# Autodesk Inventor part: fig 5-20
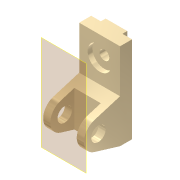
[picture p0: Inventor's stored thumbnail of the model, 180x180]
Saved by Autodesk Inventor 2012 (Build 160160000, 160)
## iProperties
Shininess: 65.0
Angle Display Precision: 2
Document Length Units: 11269
Document Angle Units: 11279
Document Time Units: 11290
Document Mass Units: 11283
Document Length Units Precision: 3
Document Angle Units Precision: 2
Compacted: False
Created: 2001-11
Part Number: fig 5-20
Document SubType Name: Modeling
Designer: Renu Muthoo
Density: 1 g/cm^3
Material: Default
Density: 0.0
Volumn: 0.0
Area: 0.0
PropertySet Name: Model Information
Control State: 0
Master: False
Checked Out: False
Author: Renu Muthoo
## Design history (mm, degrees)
node "Sketch1"
sketch "Sketch2"
  geometry: L1 (33.257, 104.664)-(33.257, -75.336); L2 (33.257, -75.336)-(8.257, -75.336); L3 (8.257, -75.336)-(-45.451, -59.045); L4 (-45.451, -1.628)-(8.257, 14.664); L5 (8.257, 14.664)-(8.257, 104.664); L6 (8.257, 104.664)-(33.257, 104.664); C1 r 15 at (-36.743, -30.336); A1 r 30 centre (-36.743, -30.336) between (-45.451, -1.628) and (-45.451, -59.045)
  constraints: 12 end point, 2 centre point, 2 equal length, 2 parallel, 2 point on circle, 2 tangent, 1 coincident, 1 perpendicular, 1 vertical
  dimensions: "d0" = 180 distance of L1.start L1.end; "d1" = 30 radius of A1; "d2" = 25 distance of L5.end L1.start; "d3" = 45 distance from line of L2 A1.centre; "d4" = 70 distance from line of L1 A1.centre; "d5" = 30 diameter of C1
extrude "Extrusion1" new body sketch "Sketch2" distance "d6" = 85; taper "d7" = 0 deg
workplane "Work Plane1"
sketch "Sketch3"
  geometry: L1 (15, 62.364)-(70, 62.364); L2 (70, 62.364)-(70, -52.386); L3 (70, -52.386)-(15, -52.386); L4 (15, -52.386)-(15, 62.364); L5 (0, -45)-(0, -28.708) reference
  constraints: 8 end point, 2 parallel, 1 horizontal, 1 perpendicular
  dimensions: "d8" = 55 distance of L1.start L1.end; "d9" = 15 distance between parallel lines of L5 L4
extrude "Extrusion2" cut sketch "Sketch3" distance "d10" = 50; taper "d11" = 0 deg
sketch "Sketch4"
  geometry: L1 (0, 25)-(85, 25) reference; L2 (0, 0)-(0, 25) reference; L3 (20, 25)-(65, 25); L4 (65, 25)-(65, 35); L5 (65, 35)-(20, 35); L6 (20, 35)-(20, 25)
  constraints: 8 end point, 2 parallel, 1 horizontal, 1 perpendicular, 1 point on line
  dimensions: "d12" = 45 distance of L4.end L5.end; "d13" = 10 distance of L3.end L4.end; "d14" = 20 distance between parallel lines of L2 L6
extrude "Extrusion3" join sketch "Sketch4" stored distance "d15" = 50; taper "d16" = 0 deg
sketch "Sketch5"
  geometry: L1 (85, 0)-(85, 90) reference; L2 (0, 90)-(85, 90) reference; 1 further point
  dimensions: "d17" = 42 distance from line of L2 point (42.5, 48); "d18" = 42.5 distance from line of L1 point (42.5, 48)
hole "Hole1" sketch "Sketch5" at (42.5, 48) diameter "d19" = 20; stored, may be unused: countersink angle "d23" = 82 deg, drill point angle "d25" = 118 deg; dims "d20" = 6, "d21" = 50, "d22" = 10, "d24" = 8
workplane "Work Plane10"
body "Solid1"
